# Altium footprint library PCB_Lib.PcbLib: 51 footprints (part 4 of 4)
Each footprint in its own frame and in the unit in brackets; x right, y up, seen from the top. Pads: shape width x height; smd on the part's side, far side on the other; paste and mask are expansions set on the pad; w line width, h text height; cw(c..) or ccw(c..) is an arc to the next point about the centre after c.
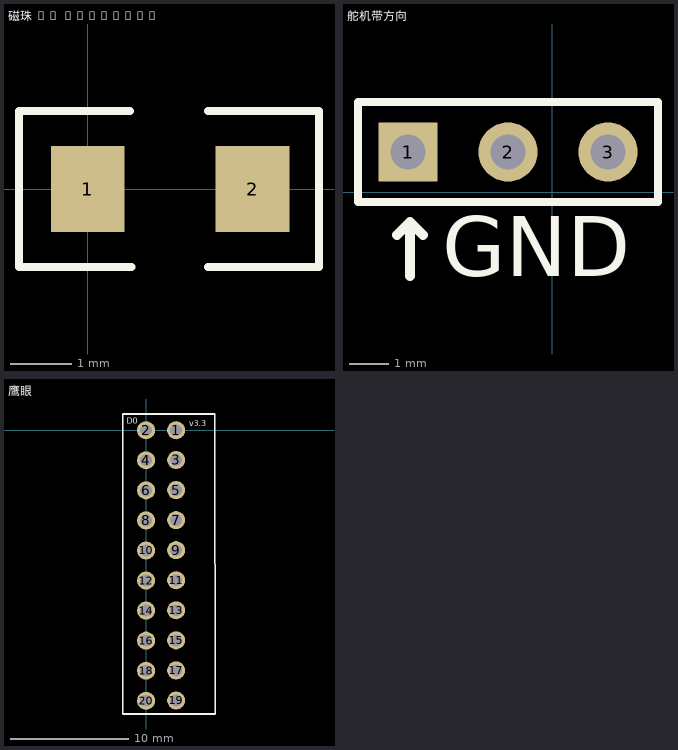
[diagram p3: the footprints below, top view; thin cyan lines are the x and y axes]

## 磁珠 F3 600@100M [mm]
pads (2):
  rect 1.2x1.4 smd: 1(0,0) 2(2.68,0)
Top Overlay:
  lines w0.127: 0.686,1.27 -1.118,1.27 -1.118,-1.27 0.711,-1.27 ; 1.956,-1.27 3.734,-1.27 3.759,-1.27 3.759,1.27 1.956,1.27

## 舵机带方向 [mm]
pads (3):
  rect 1.5x1.5 hole 0.9: 1(-3.658,1.016)
  round 1.5 hole 0.9: 2(-1.118,1.016) 3(1.422,1.016)
Top Overlay:
  lines w0.2: -4.928,-0.254 2.692,-0.254 2.692,2.286 -4.928,2.286 -4.928,-0.254
  lines w0.254: -3.937,-1.092 -3.607,-0.762 ; -3.607,-2.134 -3.607,-0.762 ; -3.277,-1.092 -3.607,-0.762
  text "GND" at -2.794,-2.134 h1.52

## 鹰眼 [mil]
pads (20):
  round 60 hole 39.37 square: 1(100,0)
  round 60 hole 39.37: 2(0,0) 3(100,-99) 4(0,-100) 5(100,-199) 6(0,-200) 7(100,-299) 8(0,-300) 9(100,-399) 10(0,-400) 11(100,-499) 12(0,-500) 13(100,-599) 14(0,-600) 15(100,-699) 16(0,-700) 17(100,-799) 18(0,-800) 19(100,-899) 20(0,-900)
Top Overlay:
  lines w5: -77,-944 -77,54 228.86,54 229.62,-944 -77,-944
  text "v3.3" at 143,14 h20
  text "D0" at -65,22 h20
